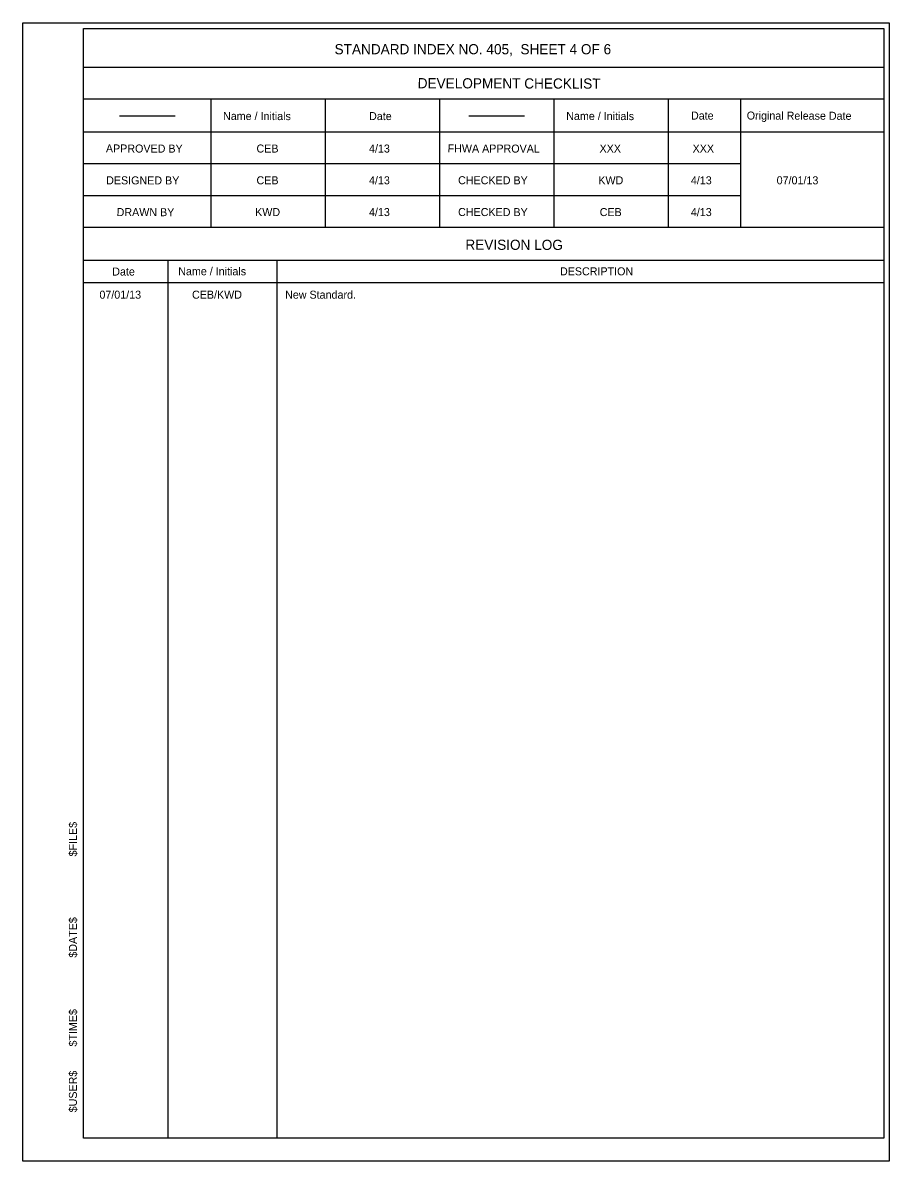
# Model space of a CAD drawing. Extents: x 1.5 to 68.7, y 0 to 31.
# Drawn here: x 46.92 to 68.73, y 0 to 28.67 of the extents above; entities that cross this region are included whole.
import ezdxf

# ---------------------------------------------------------------- set-up
doc = ezdxf.new("R2010")
doc.units = 0
for name, color, linetype in [('Border', 7, 'Continuous'), ('Dimension', 7, 'Continuous'), ('PlotBorder_dp', 7, 'Continuous'), ('TextStructures', 7, 'Continuous')]:
    doc.layers.add(name, color=color, linetype=linetype)

msp = doc.modelspace()

# ---------------------------------------------------------------- linework, layer by layer
at = {"layer": 'Border'}
for p, q in [((68.593, 27.54), (48.446, 27.54)), ((68.593, 26.74), (48.446, 26.74)), ((51.646, 26.74), (51.646, 23.512)), ((54.526, 26.74), (54.526, 23.512)), ((57.406, 26.74), (57.406, 23.512)), ((60.286, 26.74), (60.286, 23.512)), ((63.166, 26.74), (63.166, 23.512)), ((64.981, 26.74), (64.981, 23.512)), ((68.593, 25.912), (48.446, 25.912)), ((64.981, 25.112), (48.446, 25.112)), ((64.981, 24.312), (48.446, 24.312)), ((68.593, 23.512), (48.446, 23.512)), ((68.593, 22.684), (48.446, 22.684)), ((50.566, 22.684), (50.566, 0.578)), ((53.309, 22.684), (53.309, 0.578)), ((68.593, 22.121), (48.446, 22.121))]:
    msp.add_line(p, q, dxfattribs=at)
msp.add_lwpolyline([(48.446, 28.521), (68.593, 28.521), (68.593, 0.578), (48.446, 0.578)], close=True, dxfattribs=at)
at = {"layer": 'Dimension'}
for p, q in [((50.751, 26.312), (49.347, 26.312)), ((59.547, 26.312), (58.144, 26.312))]:
    msp.add_line(p, q, dxfattribs=at)
at = {"layer": 'PlotBorder_dp'}
msp.add_line((46.915, 0), (46.915, 0), dxfattribs=at)
msp.add_lwpolyline([(46.915, 28.667), (68.729, 28.667), (68.729, 0), (46.915, 0)], close=True, dxfattribs=at)

# ---------------------------------------------------------------- texts
at = {"layer": 'Dimension'}
msp.add_text('New Standard.', height=0.2016, dxfattribs=at).set_placement((53.52, 21.719))
at = {"layer": 'TextStructures'}
for s, height, p in [('STANDARD INDEX NO. 405,  SHEET 4 OF 6', 0.256, (54.765, 27.873)), ('CEB', 0.2016, (52.8, 25.399)), ('4/13', 0.2016, (55.632, 25.399)), ('XXX', 0.2016, (61.436, 25.399)), ('XXX', 0.2016, (63.779, 25.399)), ('CEB', 0.2016, (52.8, 24.599)), ('4/13', 0.2016, (55.632, 24.599)), ('KWD', 0.2016, (61.405, 24.599)), ('4/13', 0.2016, (63.735, 24.599)), ('07/01/13', 0.2016, (65.895, 24.599)), ('KWD', 0.2016, (52.765, 23.799)), ('4/13', 0.2016, (55.632, 23.799)), ('CEB', 0.2016, (61.44, 23.799)), ('4/13', 0.2016, (63.735, 23.799)), ('DESCRIPTION', 0.2016, (60.44, 22.307)), ('07/01/13', 0.2016, (48.845, 21.719)), ('CEB/KWD', 0.2016, (51.176, 21.719))]:
    msp.add_text(s, height=height, dxfattribs=at).set_placement(p)
for s, height, rotation, p in [('DEVELOPMENT CHECKLIST', 0.256, 359.8756, (56.858, 27.017)), ('Name / Initials', 0.2016, 359.8756, (51.957, 26.219)), ('Date', 0.2016, 359.8756, (55.633, 26.217)), ('Name / Initials', 0.2016, 359.8756, (60.597, 26.219)), ('Date', 0.2016, 359.8756, (63.738, 26.229)), ('Original Release Date', 0.2016, 359.8756, (65.142, 26.229)), ('APPROVED BY', 0.2016, 359.8756, (49.008, 25.401)), ('FHWA APPROVAL', 0.2016, 359.8756, (57.611, 25.401)), ('DESIGNED BY', 0.2016, 359.8756, (49.014, 24.599)), ('CHECKED BY', 0.2016, 359.8756, (57.875, 24.601)), ('DRAWN BY', 0.2016, 359.8756, (49.278, 23.799)), ('CHECKED BY', 0.2016, 359.8756, (57.875, 23.801)), ('REVISION LOG', 0.256, 359.8756, (58.059, 22.951)), ('Date', 0.2016, 359.8756, (49.168, 22.302)), ('Name / Initials', 0.2016, 359.8756, (50.829, 22.311)), ('$FILE$', 0.2016, 90, (48.279, 7.675)), ('$DATE$', 0.2016, 90, (48.279, 5.126)), ('$TIME$', 0.2016, 90, (48.279, 2.888)), ('$USER$', 0.2016, 90, (48.279, 1.231))]:
    msp.add_text(s, height=height, rotation=rotation, dxfattribs=at).set_placement(p)

doc.saveas('drawing.dxf')
